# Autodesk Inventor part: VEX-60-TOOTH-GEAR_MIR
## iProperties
Created: 2007-08
Part Number: VEX-60-TOOTH-GEAR_MIR
Material: ABS Plastic
Document SubType Name: Modeling
Mass: 9.01025 g
Surface Area: 99.3042 cm^2
Volume: 8.50023 cm^3
Density: 1.06 g/cm^3
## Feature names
1. Derived Body1 [Tagging]
